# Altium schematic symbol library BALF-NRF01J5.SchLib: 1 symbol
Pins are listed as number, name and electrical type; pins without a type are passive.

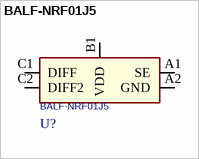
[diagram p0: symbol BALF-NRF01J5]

## BALF-NRF01J5
designator U?
footprint ST_CSP5N50x40P2x3_134x81x34
pins: A1 SE, A2 GND, B1 VDD, C1 DIFF, C2 DIFF2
